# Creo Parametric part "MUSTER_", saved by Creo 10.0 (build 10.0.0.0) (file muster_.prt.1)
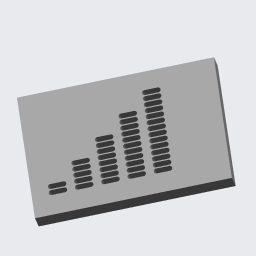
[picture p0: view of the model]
Materials in the file: S235JRG2

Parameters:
  BENENNUNG = "XXX"
  DATUM = "XX.XX.XX"
  ERSTELLER = "ARINDA"
  TEILETYP = "Fertigungsteil"
  PTC_MASTER_MATERIAL = "S235JRG2"
  SELECT_EN_NAME = "S235JRG2"
  SELECT_DIN_NAME = "RSt37-2"
  SELECT_DIN_NUMBER = "1.0038"
  SELECT_ASTM_NAME = "A 283 M Grade 2"
  MATERIAL_GROUP = "ME_ST_Baustahl"
  STANDARD_EN_DELIVERYSPEC = "DIN EN 10025"
  STANDARD_DIN_DELIVERYSPEC = "DIN 17100"

Other parameters: MASSE

Created from: ARINDA-STARTTEIL.PRT

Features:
  1. coordinate system "CS0"
  2. datum plane "DTM1", "T_RECHTS_Y-Z"
  3. datum plane "DTM2", "T_OBEN_X-Z"
  4. datum plane "DTM3", "T_VORNE_X-Y"
  5. datum axis "T_X-ACHSE"
  6. datum axis "A_1"
  7. datum axis "A_2"
  8. extrusion "Profil 1"
  9. pattern "Muster 2"
  10. pattern "Muster 1"
  11. extruded cut "Profil 2"
  12. extruded cut "Profil 2 [2]"
  13. pattern "Muster 6"
  14. extruded cut "Profil 6 [1]"
  15. extruded cut "Profil 6 [2]"
  16. extruded cut "Profil 6 [3]"
  17. extruded cut "Profil 6 [4]"
  18. extruded cut "Profil 6 [5]"
  19. pattern "Muster 7"
  20. extruded cut "Profil 7 [1]"
  21. extruded cut "Profil 7 [2]"
  22. extruded cut "Profil 7 [3]"
  23. extruded cut "Profil 7 [4]"
  24. extruded cut "Profil 7 [5]"
  25. extruded cut "Profil 7 [6]"
  26. extruded cut "Profil 7 [7]"
  27. extruded cut "Profil 7 [8]"
  28. pattern "Muster 8"
  29. extruded cut "Profil 8 [1]"
  30. extruded cut "Profil 8 [2]"
  31. extruded cut "Profil 8 [3]"
  32. extruded cut "Profil 8 [4]"
  33. extruded cut "Profil 8 [5]"
  34. extruded cut "Profil 8 [6]"
  35. extruded cut "Profil 8 [7]"
  36. extruded cut "Profil 8 [8]"
  37. extruded cut "Profil 8 [9]"
  38. extruded cut "Profil 8 [10]"
  39. extruded cut "Profil 8 [11]"
  40. pattern "Muster 9"
  41. extruded cut "Profil 9 [1]"
  42. extruded cut "Profil 9 [2]"
  43. extruded cut "Profil 9 [3]"
  44. extruded cut "Profil 9 [4]"
  45. extruded cut "Profil 9 [5]"
  46. extruded cut "Profil 9 [6]"
  47. extruded cut "Profil 9 [7]"
  48. extruded cut "Profil 9 [8]"
  49. extruded cut "Profil 9 [9]"
  50. extruded cut "Profil 9 [10]"
  51. extruded cut "Profil 9 [11]"
  52. extruded cut "Profil 9 [12]"
  53. extruded cut "Profil 9 [13]"
  54. extruded cut "Profil 9 [14]"

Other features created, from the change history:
  extruded cut "Profil 3 [3]" (2 times)
  extruded cut "Profil 3 [4]" (2 times)
  extruded cut "Profil 3 [5]" (2 times)
  extruded cut "Profil 4 [3]" (2 times)
  extruded cut "Profil 4 [4]" (2 times)
  extruded cut "Profil 4 [5]" (2 times)
  extruded cut "Profil 4 [6]" (2 times)
  extruded cut "Profil 4 [7]" (2 times)
  extruded cut "Profil 4 [8]" (2 times)
  extruded cut "Profil 5 [3]" (2 times)
  extruded cut "Profil 5 [4]" (2 times)
  extruded cut "Profil 5 [5]" (2 times)
  extruded cut "Profil 5 [6]" (2 times)
  extruded cut "Profil 5 [7]" (2 times)
  extruded cut "Profil 5 [8]" (2 times)
  extruded cut "Profil 5 [9]" (2 times)
  extruded cut "Profil 5 [10]" (2 times)
  extruded cut "Profil 5 [11]" (2 times)
  pattern "Muster 3"
  extruded cut "Profil 3 [1]"
  extruded cut "Profil 3 [2]"
  pattern "Muster 4"
  extruded cut "Profil 4 [1]"
  extruded cut "Profil 4 [2]"
  pattern "Muster 5"
  extruded cut "Profil 5 [1]"
  extruded cut "Profil 5 [2]"
  pattern "Muster 10"
  extruded cut "Profil 10 [1]"
  extruded cut "Profil 10 [2]"
  extruded cut "Profil 10 [3]"
  extruded cut "Profil 10 [4]"
  extruded cut "Profil 10 [5]"
  extruded cut "Profil 10 [6]"
  extruded cut "Profil 10 [7]"
  extruded cut "Profil 10 [8]"
  extruded cut "Profil 10 [9]"
  extruded cut "Profil 10 [10]"
  extruded cut "Profil 10 [11]"
  extruded cut "Profil 10 [12]"
  extruded cut "Profil 10 [13]"
  extruded cut "Profil 10 [14]"
  extruded cut "Profil 10 [15]"
  extruded cut "Profil 10 [16]"
  extruded cut "Profil 10 [17]"

Other named items: T_BASIC, T_Y-ACHSE, T_Z-ACHSE

Layers: 00_STD-ACHSEN, 00_STD-EBENEN, 00_STD-KOORDSYS, VOLUMENGEOMETRIE

Surfaces: 86 plane, 80 cylinder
